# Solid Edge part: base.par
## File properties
Accuracy: 0.99
Title: Base
Author: Robert a Rhodes jr
Template: Normal.par
Last saved by: TIET
Revision: 20
Application: Solid Edge
Material: aluminum
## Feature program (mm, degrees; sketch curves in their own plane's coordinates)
sketch for "unnamed Protrusion 1" plane through (0, 0, 0) normal (0, 0, 1) x-axis (1, 0, 0)
  line (-85, 25) -> (-85, -25)
  arc centre (-80, -25) radius 5 from (-85, -25) to (-80, -30) ccw
  line (-80, -30) -> (80, -30)
  arc centre (80, -25) radius 5 from (85, -25) to (80, -30) cw
  line (85, -25) -> (85, 25)
  arc centre (80, 25) radius 5 from (80, 30) to (85, 25) cw
  line (80, 30) -> (-80, 30)
  arc centre (-80, 25) radius 5 from (-85, 25) to (-80, 30) cw
extrude "unnamed Protrusion 1" add finite 20 along +normal
sketch for "ExtrudedProtrusion_2" plane through (5, -12, 10) normal (0, -1, 0) x-axis (1, 0, 0)
  line (-50, 10) -> (-50, 50)
  arc centre (15, 50) radius 65 from (-50, 50) to (-20, 104.7723) cw
  line (-20, 104.7723) -> (-20, 144)
  arc centre (-17, 144) radius 3 from (-20, 144) to (-17, 147) cw
  line (-17, 147) -> (37, 147)
  arc centre (37, 144) radius 3 from (37, 147) to (40, 144) cw
  line (40, 144) -> (40, 75)
  line (40, 75) -> (-12, 75)
  line (-12, 28.959) -> (-12, 75)
  line (10, 10) -> (-12, 28.959)
  line (28, 35) -> (10, 10)
  line (40, 35) -> (28, 35)
  line (40, 35) -> (40, 10)
extrude "ExtrudedProtrusion_2" add  Plane_Distance = 18 mm
sketch for "unnamed Cutout 1" plane through (5, -12, 88.5) normal (0, -1, 0) x-axis (1, 0, 0)
  line (-20, -68.5) -> (-20, 4.7281)
  arc centre (-25, 4.7281) radius 5 from (-28.8, 7.9777) to (-20, 4.7281) cw
  arc centre (13, -27.7681) radius 55 from (-42, -27.7681) to (-28.8, 7.9777) cw
  line (-42, -68.5) -> (-42, -27.7681)
  line (-42, -68.5) -> (-20, -68.5)
extrude "unnamed Cutout 1" cut finite 10 along -normal
sketch for "ExtrudedCutout_2" plane through (5, 0, 0) normal (0, 0, -1) x-axis (1, 0, 0)
  line (-10, 1) -> (-10, -19)
  line (-10, -19) -> (30, -19)
  line (30, -19) -> (30, 1)
  line (30, 1) -> (-10, 1)
  dimension (linear) = 10
extrude "ExtrudedCutout_2" cut finite 147 along -normal
sketch for "ExtrudedProtrusion_3" plane through (25, 9, 157) normal (0, 0, 1) x-axis (1, 0, 0)
  circle centre (-10, 0) radius 15
  dimension (linear) = 10
extrude "ExtrudedProtrusion_3" add finite 18 along +normal
sketch for "Hole_1" plane through (25, 9, 175) normal (0, 0, 1) x-axis (1, 0, 0)
  hole centre (-10, 0) bore radius 10
hole "Hole_1" diameter 20 finite
sketch for "Hole_2" plane through (45, 9, 119.9119) normal (1, 0, 0) x-axis (0, 1, 0)
  hole centre (1, 20.0881) bore radius 4
  dimension (linear) = 1
hole "Hole_2" diameter 8 through
mirror "unnamed Mirror 1" of "unnamed Cutout 1" about plane through (5, 9, 88.7059) normal (0, -1, 0)
extrude "unnamed Cutout 2" cut finite 10
fillet "Round_1" radius 3
sketch for "Hole_3" plane through (0, 0, 20) normal (0, 0, 1) x-axis (1, 0, 0)
  hole centre (70, 0) bore radius 6.5
hole "Hole_3" diameter 13 through
sketch for "unnamed Hole 1" plane through (0, 0, 20) normal (0, 0, 1) x-axis (1, 0, 0)
  hole centre (-70, 0) bore radius 6.5
  dimension (linear) = 70
  dimension (linear) = 70
hole "unnamed Hole 1" through
pattern "unnamed Pattern 1" of "Hole_3", "unnamed Hole 1"
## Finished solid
Body 1: solid body, 61 faces, 164 edges, 100 vertices.
  Faces by surface: plane 37, cylinder 23, torus 1
  Edges by curve: line 114, circle 50
Bounding box of the edges (mm; curved faces can reach further): 170.000 x 60.000 x 175.000, from (-85, -30, 0) to (85, 30, 175).
Cylindrical faces by radius (mm): R3 x8, R4 x2, R5 x6, R6.5 x2, R10 x1, R15 x1, R55 x2, R65 x1
Toroidal faces (ring radius, tube radius in mm): R18 r3 x1
Planar faces by outward normal: +x 8, +y 4, +z 5, -x 7, -y 6, -z 4, oblique 3
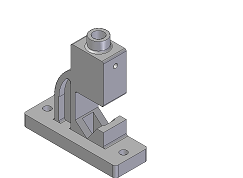
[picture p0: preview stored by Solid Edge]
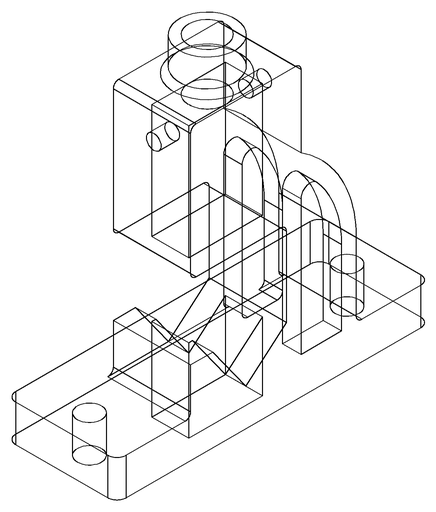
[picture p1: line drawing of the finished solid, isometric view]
